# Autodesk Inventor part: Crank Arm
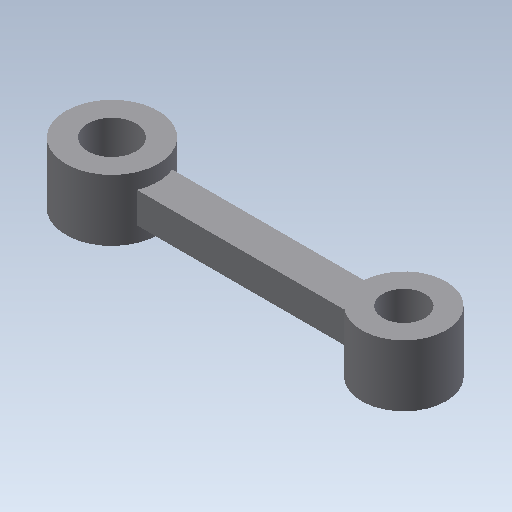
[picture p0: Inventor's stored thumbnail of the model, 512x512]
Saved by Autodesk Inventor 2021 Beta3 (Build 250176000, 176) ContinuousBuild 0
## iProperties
Created: 2012-08
Part Number: Crank Arm
Material: Generic
Document SubType Name: Modeling
Designer: John
Density: 1 g/cm^3
Appearance: Default
Author: John
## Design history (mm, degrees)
sketch "Sketch1"
  geometry: L1 (0, 1.461)-(24.13, 1.461); L2 (24.13, 1.461)-(24.13, -1.461); L3 (24.13, -1.461)-(0, -1.461); L4 (0, -1.461)-(0, 1.461); C1 r 3.81 at (0, 0); C2 r 3.493 at (24.13, 0); 2 further points
  constraints: 8 end point, 2 centre point, 2 coincident, 2 parallel, 2 vertical alignment, 1 horizontal, 1 horizontal alignment, 1 midpoint, 1 perpendicular
  dimensions: "d0" = 7.62 diameter of C1; "d1" = 2.921 distance of L1.end L2.end; "d2" = 1.4605 distance from line of C2.centre L1 (= 0.5 x d1); "d3" = 24.13 distance of C2.centre C1.centre; "d15" = 6.985 diameter of C2
extrude "Extrusion1" new body sketch "Sketch1" stored distance "d4" = 5.08; taper "d5" = 0 deg
extrude "Extrusion2" join sketch "Sketch1" stored distance "d6" = 2.54; taper "d7" = 0 deg
hole "Hole2" diameter "d18" = 3.9878; stored, may be unused: countersink angle "d22" = 82 deg, drill point angle "d24" = 118 deg; dims "d16" = 25.4, "d17" = 25.4, "d19" = 19.05, "d20" = 9.525, "d21" = 6.35, "d23" = 25.4
hole "Hole3" diameter "d27" = 3.4798; stored, may be unused: countersink angle "d31" = 82 deg, drill point angle "d33" = 118 deg; dims "d25" = 25.4, "d26" = 25.4, "d28" = 19.05, "d29" = 9.525, "d30" = 6.35, "d32" = 25.4
body "Solid1"
